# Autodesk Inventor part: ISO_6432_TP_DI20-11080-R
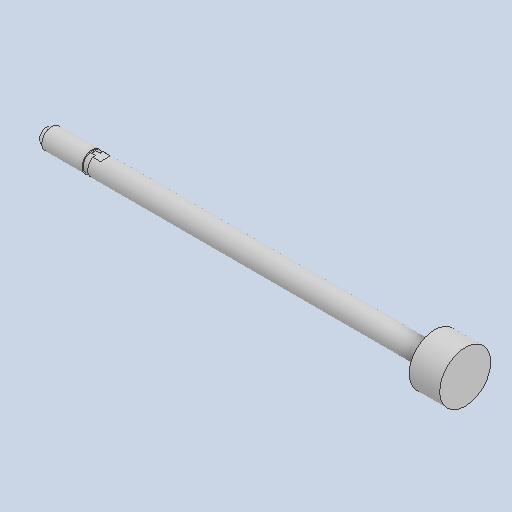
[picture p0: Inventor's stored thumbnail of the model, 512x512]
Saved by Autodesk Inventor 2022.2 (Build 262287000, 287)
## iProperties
Created: 2024-10
Part Number: ISO_6432_TP_DI20-11080-R
Material: Generico
Document SubType Name: Modeling
Designer: 18907419
Density: 1 g/cm^3
Appearance: Default
Author: 18907419
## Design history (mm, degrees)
feature "Solid1"
node "Solido1"
